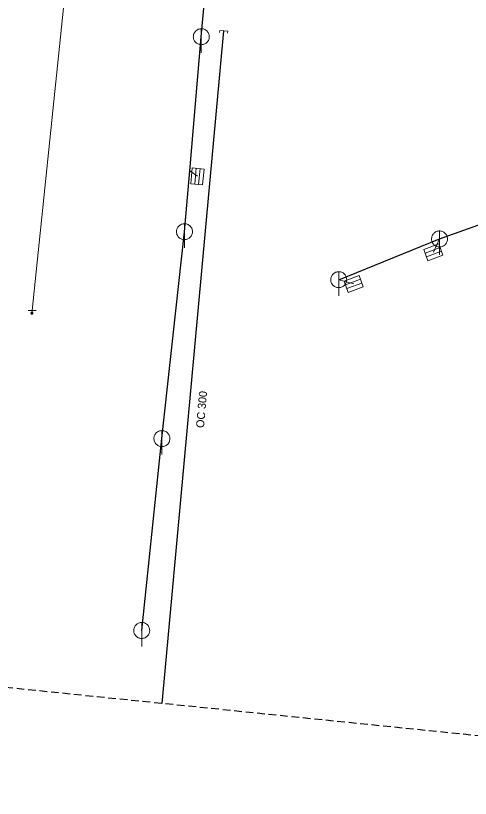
# Model space of a CAD drawing. Extents: x -725153 to -724843, y -978146 to -977794.
# Drawn here: x -725095.7 to -725038.8, y -978146.1 to -978048.3 of the extents above; entities that cross this region are included whole.
import ezdxf

# ---------------------------------------------------------------- set-up
doc = ezdxf.new("R2010")
doc.units = 0
doc.header["$LTSCALE"] = 0.32
doc.linetypes.add('MEDIUM_DASHED', pattern=[4.5, 3, -1.5])
doc.layers.add('1', color=7, linetype='Continuous')
for name, color, linetype, lineweight in [('11', 7, 'Continuous', 13), ('13', 7, 'Continuous', 13), ('14', 7, 'Continuous', 25), ('17', 7, 'Continuous', 25), ('22', 7, 'Continuous', 13), ('34', 7, 'Continuous', 13), ('47', 7, 'Continuous', 13), ('63', 7, 'MEDIUM_DASHED', 25), ('9', 7, 'Continuous', 13)]:
    doc.layers.add(name, color=color, linetype=linetype, lineweight=lineweight)

msp = doc.modelspace()

# ---------------------------------------------------------------- linework, layer by layer
at = {"layer": '11'}
for p, q in [((-725072.914, -978068.394), (-725073.886, -978067.693)), ((-725043.403, -978077.891), (-725042.636, -978076.227)), ((-725053.37, -978081.849), (-725055.249, -978081.313))]:
    msp.add_line(p, q, dxfattribs=at)
at = {"layer": '13'}
msp.add_line((-725087.312, -978024.817), (-725093.614, -978085.162), dxfattribs=at)
at = {"layer": '14'}
msp.add_line((-725072.438, -978050.944), (-725070.014, -978023.765), dxfattribs=at)
at = {"layer": '14', "lineweight": 13}
msp.add_line((-725093.614, -978085.162), (-725093.629, -978085.498), dxfattribs=at)
at = {"layer": '14'}
for points in [[(-725074.546, -978075.317), (-725073.886, -978067.693), (-725072.438, -978050.943)], [(-725055.249, -978081.313), (-725042.636, -978076.227), (-725032.901, -978072.757)], [(-725079.895, -978125.159), (-725077.365, -978101.177), (-725074.546, -978075.317)]]:
    msp.add_lwpolyline(points, dxfattribs=at)
at = {"layer": '17'}
msp.add_line((-725077.328, -978134.293), (-725069.629, -978050.219), dxfattribs=at)
at = {"layer": '22'}
for p, q in [((-725072.438, -978052.944), (-725072.437, -978049.944)), ((-725073.267, -978069.375), (-725073.073, -978067.384)), ((-725072.769, -978069.423), (-725072.575, -978067.433)), ((-725074.546, -978077.317), (-725074.545, -978074.317)), ((-725042.636, -978078.227), (-725042.635, -978075.227)), ((-725044.439, -978078.003), (-725042.566, -978077.303)), ((-725044.264, -978078.471), (-725042.391, -978077.771)), ((-725055.249, -978083.313), (-725055.248, -978080.313)), ((-725054.406, -978081.962), (-725052.533, -978081.262)), ((-725054.231, -978082.43), (-725052.358, -978081.73)), ((-725077.365, -978103.177), (-725077.364, -978100.177)), ((-725079.895, -978127.159), (-725079.894, -978124.159))]:
    msp.add_line(p, q, dxfattribs=at)
for points in [[(-725071.438, -978050.944), (-725071.443, -978050.835), (-725071.461, -978050.727), (-725071.491, -978050.621), (-725071.531, -978050.52), (-725071.583, -978050.423), (-725071.645, -978050.333), (-725071.717, -978050.25), (-725071.797, -978050.176), (-725071.885, -978050.11), (-725071.979, -978050.055), (-725072.079, -978050.01), (-725072.184, -978049.977), (-725072.291, -978049.955), (-725072.4, -978049.945), (-725072.51, -978049.947), (-725072.618, -978049.961), (-725072.725, -978049.986), (-725072.828, -978050.023), (-725072.926, -978050.072), (-725073.018, -978050.13), (-725073.104, -978050.199), (-725073.181, -978050.276), (-725073.25, -978050.362), (-725073.309, -978050.454), (-725073.357, -978050.552), (-725073.394, -978050.655), (-725073.42, -978050.762), (-725073.434, -978050.87), (-725073.437, -978050.98), (-725073.427, -978051.089), (-725073.406, -978051.196), (-725073.372, -978051.3), (-725073.328, -978051.4), (-725073.273, -978051.495), (-725073.207, -978051.583), (-725073.133, -978051.663), (-725073.05, -978051.735), (-725072.96, -978051.797), (-725072.864, -978051.849), (-725072.762, -978051.89), (-725072.657, -978051.92), (-725072.549, -978051.938), (-725072.439, -978051.944), (-725072.33, -978051.938), (-725072.222, -978051.92), (-725072.117, -978051.891), (-725072.015, -978051.85), (-725071.918, -978051.798), (-725071.828, -978051.736), (-725071.745, -978051.665), (-725071.67, -978051.585), (-725071.605, -978051.497), (-725071.549, -978051.403), (-725071.505, -978051.303), (-725071.471, -978051.199), (-725071.449, -978051.091), (-725071.439, -978050.982)], [(-725073.764, -978069.326), (-725073.571, -978067.336), (-725072.078, -978067.481), (-725072.271, -978069.472)], [(-725073.546, -978075.317), (-725073.551, -978075.208), (-725073.569, -978075.1), (-725073.599, -978074.994), (-725073.639, -978074.893), (-725073.691, -978074.796), (-725073.753, -978074.706), (-725073.825, -978074.623), (-725073.905, -978074.549), (-725073.993, -978074.483), (-725074.087, -978074.428), (-725074.187, -978074.383), (-725074.292, -978074.35), (-725074.399, -978074.328), (-725074.508, -978074.318), (-725074.618, -978074.32), (-725074.726, -978074.334), (-725074.833, -978074.359), (-725074.936, -978074.396), (-725075.034, -978074.445), (-725075.126, -978074.503), (-725075.212, -978074.572), (-725075.289, -978074.649), (-725075.358, -978074.735), (-725075.417, -978074.827), (-725075.465, -978074.925), (-725075.502, -978075.028), (-725075.528, -978075.135), (-725075.542, -978075.243), (-725075.545, -978075.353), (-725075.535, -978075.462), (-725075.514, -978075.569), (-725075.48, -978075.673), (-725075.436, -978075.773), (-725075.381, -978075.868), (-725075.315, -978075.956), (-725075.241, -978076.036), (-725075.158, -978076.108), (-725075.068, -978076.17), (-725074.972, -978076.222), (-725074.87, -978076.263), (-725074.765, -978076.293), (-725074.657, -978076.311), (-725074.547, -978076.317), (-725074.438, -978076.311), (-725074.33, -978076.293), (-725074.225, -978076.264), (-725074.123, -978076.223), (-725074.026, -978076.171), (-725073.936, -978076.109), (-725073.853, -978076.038), (-725073.778, -978075.958), (-725073.713, -978075.87), (-725073.657, -978075.776), (-725073.613, -978075.676), (-725073.579, -978075.572), (-725073.557, -978075.464), (-725073.547, -978075.355)], [(-725041.636, -978076.227), (-725041.641, -978076.118), (-725041.659, -978076.01), (-725041.689, -978075.904), (-725041.729, -978075.803), (-725041.781, -978075.706), (-725041.843, -978075.616), (-725041.915, -978075.533), (-725041.995, -978075.459), (-725042.083, -978075.393), (-725042.177, -978075.338), (-725042.277, -978075.293), (-725042.382, -978075.26), (-725042.489, -978075.238), (-725042.598, -978075.228), (-725042.708, -978075.23), (-725042.816, -978075.244), (-725042.923, -978075.269), (-725043.026, -978075.306), (-725043.124, -978075.355), (-725043.216, -978075.413), (-725043.302, -978075.482), (-725043.379, -978075.559), (-725043.448, -978075.645), (-725043.507, -978075.737), (-725043.555, -978075.835), (-725043.592, -978075.938), (-725043.618, -978076.045), (-725043.632, -978076.153), (-725043.635, -978076.263), (-725043.625, -978076.372), (-725043.604, -978076.479), (-725043.57, -978076.583), (-725043.526, -978076.683), (-725043.471, -978076.778), (-725043.405, -978076.866), (-725043.331, -978076.946), (-725043.248, -978077.018), (-725043.158, -978077.08), (-725043.062, -978077.132), (-725042.96, -978077.173), (-725042.855, -978077.203), (-725042.747, -978077.221), (-725042.637, -978077.227), (-725042.528, -978077.221), (-725042.42, -978077.203), (-725042.315, -978077.174), (-725042.213, -978077.133), (-725042.116, -978077.081), (-725042.026, -978077.019), (-725041.943, -978076.948), (-725041.868, -978076.868), (-725041.803, -978076.78), (-725041.747, -978076.686), (-725041.703, -978076.586), (-725041.669, -978076.482), (-725041.647, -978076.374), (-725041.637, -978076.265)], [(-725044.614, -978077.535), (-725042.741, -978076.835), (-725042.216, -978078.24), (-725044.089, -978078.94)], [(-725054.249, -978081.313), (-725054.254, -978081.204), (-725054.272, -978081.096), (-725054.302, -978080.99), (-725054.342, -978080.889), (-725054.394, -978080.792), (-725054.456, -978080.702), (-725054.528, -978080.619), (-725054.608, -978080.545), (-725054.696, -978080.479), (-725054.79, -978080.424), (-725054.89, -978080.379), (-725054.995, -978080.346), (-725055.102, -978080.324), (-725055.211, -978080.314), (-725055.321, -978080.316), (-725055.429, -978080.33), (-725055.536, -978080.355), (-725055.639, -978080.392), (-725055.737, -978080.441), (-725055.829, -978080.499), (-725055.915, -978080.568), (-725055.992, -978080.645), (-725056.061, -978080.731), (-725056.12, -978080.823), (-725056.168, -978080.921), (-725056.205, -978081.024), (-725056.231, -978081.131), (-725056.245, -978081.239), (-725056.248, -978081.349), (-725056.238, -978081.458), (-725056.217, -978081.565), (-725056.183, -978081.669), (-725056.139, -978081.769), (-725056.084, -978081.864), (-725056.018, -978081.952), (-725055.944, -978082.032), (-725055.861, -978082.104), (-725055.771, -978082.166), (-725055.675, -978082.218), (-725055.573, -978082.259), (-725055.468, -978082.289), (-725055.36, -978082.307), (-725055.25, -978082.313), (-725055.141, -978082.307), (-725055.033, -978082.289), (-725054.928, -978082.26), (-725054.826, -978082.219), (-725054.729, -978082.167), (-725054.639, -978082.105), (-725054.556, -978082.034), (-725054.481, -978081.954), (-725054.416, -978081.866), (-725054.36, -978081.772), (-725054.316, -978081.672), (-725054.282, -978081.568), (-725054.26, -978081.46), (-725054.25, -978081.351)], [(-725054.581, -978081.494), (-725052.708, -978080.794), (-725052.183, -978082.199), (-725054.056, -978082.899)], [(-725076.365, -978101.177), (-725076.37, -978101.068), (-725076.388, -978100.96), (-725076.418, -978100.854), (-725076.458, -978100.753), (-725076.51, -978100.656), (-725076.572, -978100.566), (-725076.644, -978100.483), (-725076.724, -978100.409), (-725076.812, -978100.343), (-725076.906, -978100.288), (-725077.006, -978100.243), (-725077.111, -978100.21), (-725077.218, -978100.188), (-725077.327, -978100.178), (-725077.437, -978100.18), (-725077.545, -978100.194), (-725077.652, -978100.219), (-725077.755, -978100.256), (-725077.853, -978100.305), (-725077.945, -978100.363), (-725078.031, -978100.432), (-725078.108, -978100.509), (-725078.177, -978100.595), (-725078.236, -978100.687), (-725078.284, -978100.785), (-725078.321, -978100.888), (-725078.347, -978100.995), (-725078.361, -978101.103), (-725078.364, -978101.213), (-725078.354, -978101.322), (-725078.333, -978101.429), (-725078.299, -978101.533), (-725078.255, -978101.633), (-725078.2, -978101.728), (-725078.134, -978101.816), (-725078.06, -978101.896), (-725077.977, -978101.968), (-725077.887, -978102.03), (-725077.791, -978102.082), (-725077.689, -978102.123), (-725077.584, -978102.153), (-725077.476, -978102.171), (-725077.366, -978102.177), (-725077.257, -978102.171), (-725077.149, -978102.153), (-725077.044, -978102.124), (-725076.942, -978102.083), (-725076.845, -978102.031), (-725076.755, -978101.969), (-725076.672, -978101.898), (-725076.597, -978101.818), (-725076.532, -978101.73), (-725076.476, -978101.636), (-725076.432, -978101.536), (-725076.398, -978101.432), (-725076.376, -978101.324), (-725076.366, -978101.215)], [(-725078.895, -978125.159), (-725078.9, -978125.05), (-725078.918, -978124.942), (-725078.948, -978124.836), (-725078.988, -978124.735), (-725079.04, -978124.638), (-725079.102, -978124.548), (-725079.174, -978124.465), (-725079.254, -978124.391), (-725079.342, -978124.325), (-725079.436, -978124.27), (-725079.536, -978124.225), (-725079.641, -978124.192), (-725079.748, -978124.17), (-725079.857, -978124.16), (-725079.967, -978124.162), (-725080.075, -978124.176), (-725080.182, -978124.201), (-725080.285, -978124.238), (-725080.383, -978124.287), (-725080.475, -978124.345), (-725080.561, -978124.414), (-725080.638, -978124.491), (-725080.707, -978124.577), (-725080.766, -978124.669), (-725080.814, -978124.767), (-725080.851, -978124.87), (-725080.877, -978124.977), (-725080.891, -978125.085), (-725080.894, -978125.195), (-725080.884, -978125.304), (-725080.863, -978125.411), (-725080.829, -978125.515), (-725080.785, -978125.615), (-725080.73, -978125.71), (-725080.664, -978125.798), (-725080.59, -978125.878), (-725080.507, -978125.95), (-725080.417, -978126.012), (-725080.321, -978126.064), (-725080.219, -978126.105), (-725080.114, -978126.135), (-725080.006, -978126.153), (-725079.896, -978126.159), (-725079.787, -978126.153), (-725079.679, -978126.135), (-725079.574, -978126.106), (-725079.472, -978126.065), (-725079.375, -978126.013), (-725079.285, -978125.951), (-725079.202, -978125.88), (-725079.127, -978125.8), (-725079.062, -978125.712), (-725079.006, -978125.618), (-725078.962, -978125.518), (-725078.928, -978125.414), (-725078.906, -978125.306), (-725078.896, -978125.197)]]:
    msp.add_lwpolyline(points, close=True, dxfattribs=at)
at = {"layer": '34'}
msp.add_line((-725093.114, -978085.17), (-725094.113, -978085.152), dxfattribs=at)
at = {"layer": '47'}
msp.add_lwpolyline([(-725070.145, -978050.424), (-725070.122, -978050.173), (-725069.135, -978050.264), (-725069.158, -978050.515)], dxfattribs=at)
at = {"layer": '63'}
msp.add_lwpolyline([(-725126.038, -977904.704), (-725126.038, -977794.451), (-724874.829, -977812.594), (-724855.29, -977827.945), (-724842.73, -977919.358), (-724859.477, -977998.21), (-724911.114, -978092.413), (-724961.356, -978146.144), (-725152.554, -978126.605)], close=True, dxfattribs=at)
at = {"layer": '9'}
for points in [[(-725093.755, -978085.498), (-725093.755, -978085.511), (-725093.752, -978085.524), (-725093.75, -978085.537), (-725093.745, -978085.549), (-725093.739, -978085.561), (-725093.732, -978085.572), (-725093.723, -978085.582), (-725093.713, -978085.592), (-725093.703, -978085.6), (-725093.693, -978085.607), (-725093.681, -978085.613), (-725093.669, -978085.618), (-725093.656, -978085.621), (-725093.642, -978085.623), (-725093.63, -978085.625), (-725093.617, -978085.624), (-725093.603, -978085.622), (-725093.591, -978085.619), (-725093.578, -978085.614), (-725093.566, -978085.608), (-725093.556, -978085.601), (-725093.546, -978085.593), (-725093.536, -978085.583), (-725093.527, -978085.573), (-725093.521, -978085.562), (-725093.515, -978085.55), (-725093.51, -978085.538), (-725093.507, -978085.525), (-725093.505, -978085.512), (-725093.502, -978085.499), (-725093.504, -978085.486), (-725093.505, -978085.473), (-725093.509, -978085.46), (-725093.514, -978085.448), (-725093.519, -978085.436), (-725093.527, -978085.425), (-725093.534, -978085.415), (-725093.544, -978085.405), (-725093.554, -978085.397), (-725093.566, -978085.39), (-725093.578, -978085.384), (-725093.59, -978085.379), (-725093.603, -978085.376), (-725093.615, -978085.374), (-725093.629, -978085.373), (-725093.642, -978085.373), (-725093.654, -978085.375), (-725093.668, -978085.378), (-725093.679, -978085.383), (-725093.691, -978085.389), (-725093.703, -978085.396), (-725093.713, -978085.404), (-725093.723, -978085.414), (-725093.73, -978085.424), (-725093.738, -978085.435), (-725093.744, -978085.447), (-725093.749, -978085.459), (-725093.752, -978085.472), (-725093.754, -978085.485)], [(-725093.735, -978085.498), (-725093.735, -978085.509), (-725093.733, -978085.52), (-725093.73, -978085.531), (-725093.727, -978085.541), (-725093.722, -978085.551), (-725093.716, -978085.56), (-725093.708, -978085.569), (-725093.701, -978085.577), (-725093.691, -978085.584), (-725093.683, -978085.59), (-725093.673, -978085.595), (-725093.663, -978085.599), (-725093.652, -978085.602), (-725093.641, -978085.605), (-725093.63, -978085.605), (-725093.619, -978085.605), (-725093.608, -978085.603), (-725093.597, -978085.6), (-725093.587, -978085.596), (-725093.576, -978085.591), (-725093.568, -978085.585), (-725093.559, -978085.578), (-725093.551, -978085.57), (-725093.544, -978085.561), (-725093.538, -978085.552), (-725093.532, -978085.542), (-725093.529, -978085.532), (-725093.526, -978085.521), (-725093.524, -978085.51), (-725093.522, -978085.499), (-725093.522, -978085.488), (-725093.524, -978085.477), (-725093.527, -978085.466), (-725093.532, -978085.456), (-725093.537, -978085.446), (-725093.543, -978085.437), (-725093.549, -978085.428), (-725093.558, -978085.42), (-725093.566, -978085.413), (-725093.576, -978085.407), (-725093.586, -978085.402), (-725093.595, -978085.398), (-725093.607, -978085.395), (-725093.617, -978085.393), (-725093.629, -978085.393), (-725093.64, -978085.392), (-725093.651, -978085.394), (-725093.662, -978085.397), (-725093.671, -978085.401), (-725093.681, -978085.406), (-725093.691, -978085.412), (-725093.7, -978085.419), (-725093.708, -978085.427), (-725093.715, -978085.436), (-725093.72, -978085.445), (-725093.725, -978085.455), (-725093.73, -978085.465), (-725093.733, -978085.476), (-725093.735, -978085.487)], [(-725093.716, -978085.498), (-725093.716, -978085.507), (-725093.715, -978085.516), (-725093.712, -978085.525), (-725093.708, -978085.533), (-725093.705, -978085.541), (-725093.7, -978085.549), (-725093.693, -978085.556), (-725093.688, -978085.562), (-725093.681, -978085.568), (-725093.673, -978085.573), (-725093.664, -978085.577), (-725093.657, -978085.58), (-725093.647, -978085.583), (-725093.639, -978085.584), (-725093.63, -978085.586), (-725093.62, -978085.585), (-725093.612, -978085.584), (-725093.603, -978085.581), (-725093.595, -978085.578), (-725093.587, -978085.574), (-725093.578, -978085.569), (-725093.571, -978085.563), (-725093.566, -978085.557), (-725093.559, -978085.55), (-725093.554, -978085.542), (-725093.551, -978085.534), (-725093.548, -978085.526), (-725093.544, -978085.517), (-725093.544, -978085.508), (-725093.541, -978085.499), (-725093.543, -978085.49), (-725093.544, -978085.481), (-725093.546, -978085.472), (-725093.549, -978085.464), (-725093.554, -978085.456), (-725093.559, -978085.448), (-725093.565, -978085.441), (-725093.571, -978085.435), (-725093.578, -978085.429), (-725093.586, -978085.424), (-725093.593, -978085.42), (-725093.602, -978085.417), (-725093.61, -978085.414), (-725093.62, -978085.413), (-725093.629, -978085.412), (-725093.637, -978085.412), (-725093.647, -978085.413), (-725093.656, -978085.416), (-725093.664, -978085.419), (-725093.671, -978085.423), (-725093.679, -978085.428), (-725093.686, -978085.434), (-725093.693, -978085.44), (-725093.698, -978085.447), (-725093.703, -978085.455), (-725093.708, -978085.463), (-725093.711, -978085.471), (-725093.713, -978085.48), (-725093.715, -978085.489)], [(-725093.696, -978085.498), (-725093.696, -978085.505), (-725093.695, -978085.512), (-725093.693, -978085.519), (-725093.691, -978085.525), (-725093.688, -978085.531), (-725093.684, -978085.537), (-725093.679, -978085.543), (-725093.674, -978085.548), (-725093.669, -978085.552), (-725093.663, -978085.556), (-725093.657, -978085.559), (-725093.651, -978085.562), (-725093.644, -978085.563), (-725093.637, -978085.566), (-725093.63, -978085.566), (-725093.622, -978085.566), (-725093.615, -978085.564), (-725093.608, -978085.563), (-725093.603, -978085.56), (-725093.595, -978085.557), (-725093.591, -978085.553), (-725093.585, -978085.549), (-725093.58, -978085.544), (-725093.576, -978085.538), (-725093.571, -978085.532), (-725093.568, -978085.526), (-725093.566, -978085.52), (-725093.564, -978085.513), (-725093.563, -978085.506), (-725093.561, -978085.499), (-725093.561, -978085.492), (-725093.563, -978085.485), (-725093.565, -978085.478), (-725093.568, -978085.472), (-725093.571, -978085.465), (-725093.575, -978085.46), (-725093.578, -978085.454), (-725093.583, -978085.449), (-725093.59, -978085.445), (-725093.595, -978085.441), (-725093.602, -978085.438), (-725093.608, -978085.435), (-725093.615, -978085.433), (-725093.622, -978085.432), (-725093.629, -978085.432), (-725093.636, -978085.432), (-725093.642, -978085.432), (-725093.649, -978085.434), (-725093.656, -978085.437), (-725093.662, -978085.44), (-725093.668, -978085.444), (-725093.674, -978085.448), (-725093.679, -978085.453), (-725093.683, -978085.459), (-725093.686, -978085.464), (-725093.69, -978085.471), (-725093.693, -978085.477), (-725093.693, -978085.484), (-725093.696, -978085.491)], [(-725093.676, -978085.498), (-725093.676, -978085.503), (-725093.676, -978085.508), (-725093.674, -978085.513), (-725093.673, -978085.517), (-725093.671, -978085.522), (-725093.668, -978085.526), (-725093.664, -978085.529), (-725093.661, -978085.533), (-725093.657, -978085.536), (-725093.654, -978085.539), (-725093.649, -978085.541), (-725093.644, -978085.543), (-725093.64, -978085.544), (-725093.635, -978085.546), (-725093.63, -978085.546), (-725093.625, -978085.546), (-725093.62, -978085.545), (-725093.615, -978085.544), (-725093.61, -978085.542), (-725093.605, -978085.54), (-725093.602, -978085.537), (-725093.598, -978085.534), (-725093.595, -978085.53), (-725093.592, -978085.527), (-725093.588, -978085.523), (-725093.587, -978085.518), (-725093.585, -978085.514), (-725093.583, -978085.509), (-725093.583, -978085.504), (-725093.581, -978085.499), (-725093.581, -978085.494), (-725093.583, -978085.489), (-725093.583, -978085.484), (-725093.586, -978085.48), (-725093.588, -978085.475), (-725093.591, -978085.471), (-725093.593, -978085.467), (-725093.597, -978085.464), (-725093.6, -978085.461), (-725093.605, -978085.458), (-725093.61, -978085.456), (-725093.614, -978085.454), (-725093.619, -978085.453), (-725093.624, -978085.452), (-725093.629, -978085.452), (-725093.634, -978085.452), (-725093.639, -978085.453), (-725093.644, -978085.453), (-725093.647, -978085.455), (-725093.652, -978085.457), (-725093.657, -978085.46), (-725093.659, -978085.463), (-725093.664, -978085.466), (-725093.666, -978085.47), (-725093.669, -978085.474), (-725093.671, -978085.479), (-725093.674, -978085.483), (-725093.674, -978085.488), (-725093.676, -978085.493)], [(-725093.656, -978085.498), (-725093.656, -978085.501), (-725093.657, -978085.504), (-725093.656, -978085.506), (-725093.654, -978085.509), (-725093.654, -978085.512), (-725093.652, -978085.514), (-725093.649, -978085.516), (-725093.647, -978085.518), (-725093.646, -978085.52), (-725093.644, -978085.522), (-725093.641, -978085.524), (-725093.637, -978085.525), (-725093.636, -978085.525), (-725093.632, -978085.526), (-725093.63, -978085.526), (-725093.627, -978085.526), (-725093.624, -978085.526), (-725093.62, -978085.525), (-725093.619, -978085.524), (-725093.615, -978085.523), (-725093.614, -978085.521), (-725093.61, -978085.519), (-725093.608, -978085.517), (-725093.608, -978085.515), (-725093.605, -978085.513), (-725093.605, -978085.51), (-725093.603, -978085.507), (-725093.603, -978085.505), (-725093.602, -978085.502), (-725093.6, -978085.499), (-725093.602, -978085.496), (-725093.602, -978085.493), (-725093.603, -978085.49), (-725093.603, -978085.488), (-725093.605, -978085.485), (-725093.607, -978085.483), (-725093.608, -978085.48), (-725093.61, -978085.478), (-725093.613, -978085.477), (-725093.615, -978085.475), (-725093.617, -978085.474), (-725093.62, -978085.473), (-725093.622, -978085.472), (-725093.625, -978085.472), (-725093.629, -978085.471), (-725093.632, -978085.472), (-725093.635, -978085.471), (-725093.637, -978085.473), (-725093.64, -978085.473), (-725093.642, -978085.474), (-725093.644, -978085.476), (-725093.647, -978085.477), (-725093.649, -978085.479), (-725093.651, -978085.482), (-725093.652, -978085.484), (-725093.654, -978085.487), (-725093.654, -978085.489), (-725093.656, -978085.492), (-725093.656, -978085.495)], [(-725093.637, -978085.498), (-725093.637, -978085.5), (-725093.637, -978085.5), (-725093.636, -978085.5), (-725093.636, -978085.502), (-725093.637, -978085.503), (-725093.635, -978085.503), (-725093.635, -978085.503), (-725093.635, -978085.505), (-725093.635, -978085.505), (-725093.634, -978085.506), (-725093.632, -978085.506), (-725093.632, -978085.506), (-725093.632, -978085.507), (-725093.63, -978085.507), (-725093.63, -978085.507), (-725093.629, -978085.507), (-725093.627, -978085.507), (-725093.627, -978085.506), (-725093.627, -978085.506), (-725093.625, -978085.506), (-725093.625, -978085.505), (-725093.625, -978085.505), (-725093.624, -978085.504), (-725093.624, -978085.504), (-725093.622, -978085.503), (-725093.622, -978085.502), (-725093.62, -978085.501), (-725093.62, -978085.501), (-725093.62, -978085.5), (-725093.62, -978085.499), (-725093.62, -978085.498), (-725093.62, -978085.497), (-725093.62, -978085.497), (-725093.622, -978085.496), (-725093.622, -978085.495), (-725093.622, -978085.494), (-725093.622, -978085.494), (-725093.624, -978085.493), (-725093.624, -978085.493), (-725093.625, -978085.492), (-725093.625, -978085.492), (-725093.627, -978085.491), (-725093.627, -978085.491), (-725093.627, -978085.491), (-725093.629, -978085.491), (-725093.63, -978085.491), (-725093.63, -978085.491), (-725093.63, -978085.491), (-725093.632, -978085.492), (-725093.632, -978085.491), (-725093.634, -978085.493), (-725093.634, -978085.493), (-725093.635, -978085.493), (-725093.635, -978085.493), (-725093.636, -978085.495), (-725093.636, -978085.496), (-725093.636, -978085.497), (-725093.637, -978085.497), (-725093.637, -978085.498)]]:
    msp.add_lwpolyline(points, close=True, dxfattribs=at)

# ---------------------------------------------------------------- texts
at = {"layer": '1'}
msp.add_text('OC 300', height=1, rotation=85, dxfattribs=at).set_placement((-725072.11, -978099.874))

doc.saveas('drawing.dxf')
